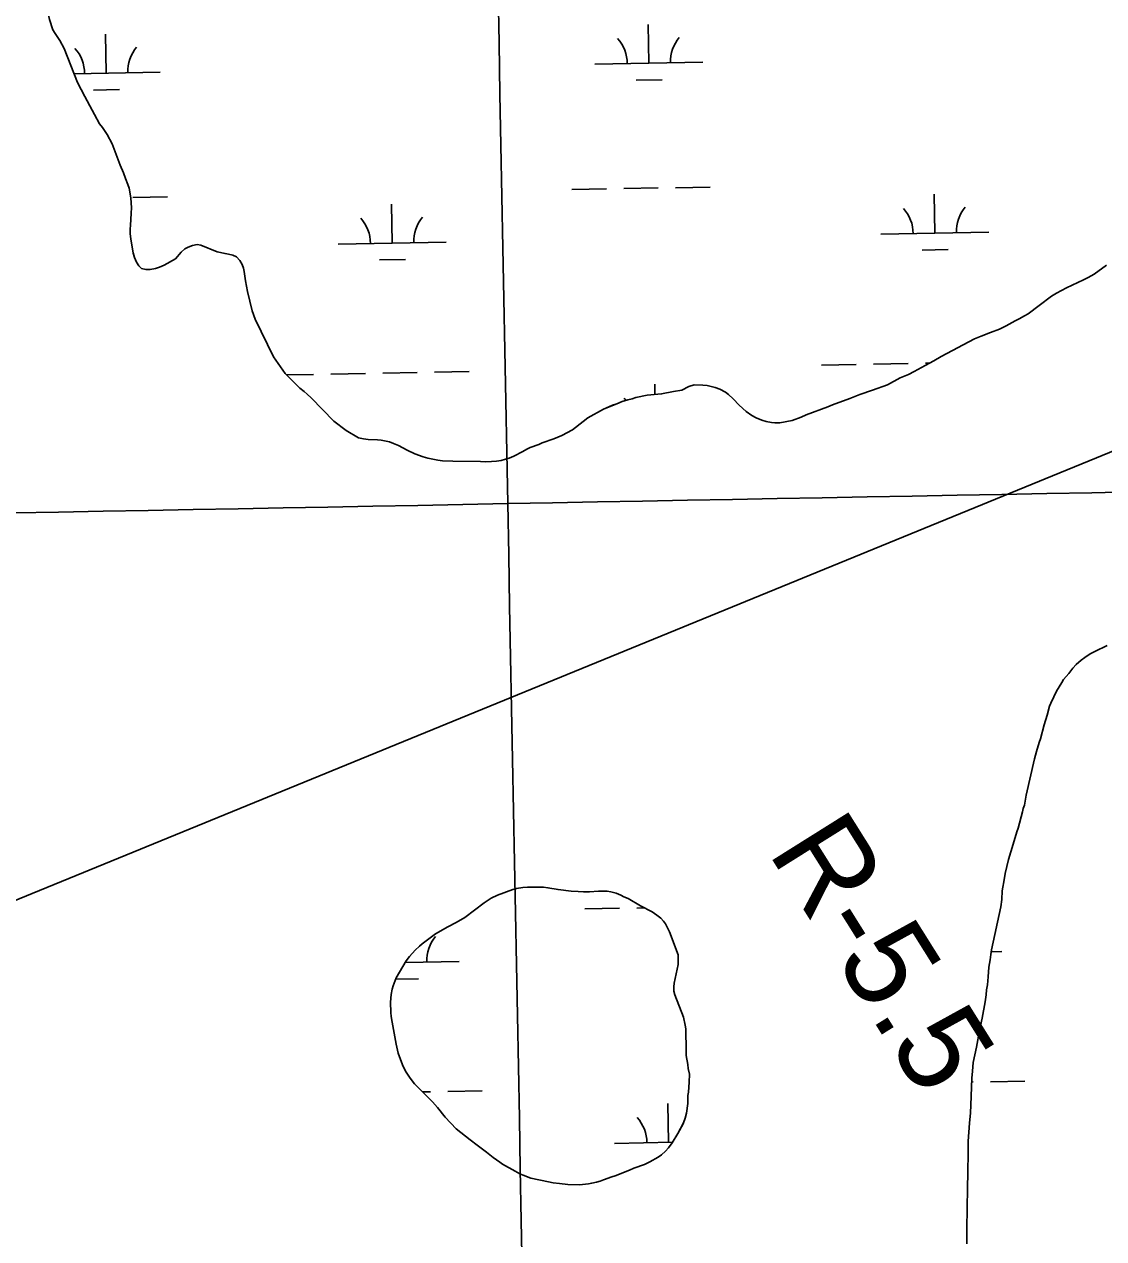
# Model space of a CAD drawing. Extents: x 3957609 to 3995875, y 234277 to 260273.
# Drawn here: x 3971894 to 3972892, y 248308 to 249431 of the extents above; entities that cross this region are included whole.
import ezdxf

# ---------------------------------------------------------------- set-up
doc = ezdxf.new("R2010")
doc.units = 0
for name, color, linetype in [('V-GRID-MAJR', 7, 'Continuous'), ('V-RIVR-RANG-IDEN', 7, 'Continuous'), ('V-TOPO-SHOR', 7, 'Continuous'), ('V-UTIL-LINE', 7, 'Continuous'), ('V-WETL-SWMP', 7, 'Continuous')]:
    doc.layers.add(name, color=color, linetype=linetype)

msp = doc.modelspace()

# ---------------------------------------------------------------- linework, layer by layer
at = {"layer": 'V-GRID-MAJR'}
for points in [[(3972513.068, 239900.828), (3972455.83, 242927.648), (3972341.236, 248987.469), (3972226.642, 255047.279), (3972169.287, 258080.274)], [(3961703.892, 248787.859), (3967022.571, 248887.277), (3972341.236, 248987.469), (3977659.886, 249088.434), (3982978.522, 249190.173), (3988297.143, 249292.685), (3993615.748, 249395.971), (3993615.749, 249395.971)]]:
    msp.add_spline(points, degree=3, dxfattribs=at)
at = {"layer": 'V-TOPO-SHOR'}
for points in [[(3971943.26, 249377.053), (3971930.929, 249408.423), (3971927.134, 249415.652), (3971922.706, 249422.265), (3971920.73, 249425.724), (3971917.592, 249435.129), (3971913.912, 249450.153), (3971911.655, 249455.957), (3971909.298, 249465.347), (3971908.255, 249468.794), (3971906.965, 249476.611), (3971906.091, 249480.834), (3971905.673, 249484.27), (3971905.583, 249488.794), (3971904.374, 249502.223), (3971904.288, 249507.058), (3971904.583, 249527.327), (3971905.333, 249535.894), (3971906.328, 249540.091), (3971910.924, 249555.774), (3971912.597, 249563.704), (3971912.251, 249564.875)], [(3972072.607, 249220.316), (3972057.569, 249226.46), (3972054.145, 249226.978), (3972049.768, 249226.261), (3972045.688, 249224.604), (3972042.705, 249223.089), (3972039.229, 249220.021), (3972033.994, 249214.014), (3972023.459, 249208.085), (3972019.378, 249206.117), (3972015.46, 249204.925), (3972010.614, 249204.061), (3972006.713, 249203.961), (3972002.672, 249204.956), (3972000.213, 249207.332), (3971998.081, 249210.793), (3971996.117, 249215.188), (3971994.927, 249219.259), (3971992.619, 249232.082), (3971992.072, 249237.392), (3971992.133, 249241.601), (3971992.49, 249244.716), (3971993.122, 249256.09), (3971993.192, 249260.924), (3971992.86, 249270.285), (3971991.122, 249279.356), (3971990.077, 249282.647), (3971987.82, 249288.293), (3971986.022, 249293.311), (3971983.007, 249300.528), (3971975.342, 249320.289), (3971970.787, 249328.932), (3971966.668, 249335.229), (3971963.756, 249338.705), (3971959.046, 249347.194), (3971957.078, 249351.277), (3971950.086, 249363.854), (3971943.26, 249377.053)], [(3972787.81, 249145.832), (3972779.18, 249142.213), (3972772.753, 249139.969), (3972741.945, 249123.417), (3972735.183, 249119.46), (3972727.171, 249115.366), (3972717.105, 249109.587), (3972711.919, 249106.855), (3972704.231, 249103.69), (3972692.445, 249097.469), (3972678.647, 249092.365), (3972666.736, 249088.328), (3972657.483, 249084.72), (3972641.646, 249078.869), (3972637.409, 249077.058), (3972617.339, 249069.552), (3972612.472, 249067.439), (3972604.162, 249064.285), (3972592.904, 249062.266), (3972588.382, 249062.175), (3972585.111, 249062.534), (3972580.135, 249063.541), (3972576.252, 249064.535), (3972570.982, 249066.949), (3972567.115, 249069.034), (3972561.711, 249072.698), (3972555.401, 249078.562), (3972549.716, 249084.415), (3972545.407, 249088.376), (3972542.632, 249090.6), (3972537.368, 249093.326), (3972533.182, 249094.948), (3972525.564, 249096.617), (3972521.672, 249097.141), (3972513.566, 249097.26), (3972508.868, 249095.924), (3972502.268, 249092.433), (3972494.45, 249091.142), (3972483.502, 249088.961), (3972470.231, 249087.907), (3972459.751, 249085.719), (3972456.3, 249084.368), (3972452.389, 249083.489), (3972447.217, 249081.849), (3972442.042, 249079.739), (3972438.122, 249078.394), (3972429.807, 249074.926), (3972415.34, 249066.716), (3972411.08, 249063.347), (3972400.992, 249055.851), (3972391.245, 249050.535), (3972383.871, 249047.522), (3972373.211, 249043.623), (3972370.071, 249042.265), (3972361.918, 249039.264), (3972358.934, 249037.905), (3972355.16, 249035.619), (3972346.99, 249031.527), (3972342.595, 249029.563), (3972339.304, 249028.521), (3972335.235, 249027.488), (3972330.856, 249026.614), (3972326.174, 249026.372), (3972320.559, 249026.297), (3972316.039, 249026.52), (3972290.625, 249026.888), (3972280.961, 249027.183), (3972276.6, 249027.716), (3972267.272, 249029.565), (3972262.922, 249030.72), (3972255.477, 249033.637), (3972248.197, 249037.018), (3972240.148, 249041.19), (3972235.655, 249043.125), (3972231.776, 249044.585), (3972224.313, 249046.097), (3972220.889, 249046.615), (3972212.16, 249046.897), (3972207.802, 249047.43), (3972203.137, 249048.431), (3972191.692, 249054.991), (3972180.59, 249063.732), (3972159.383, 249085.404), (3972155.689, 249088.734), (3972152.92, 249091.267), (3972149.063, 249094.286), (3972135.538, 249107.895), (3972124.534, 249123.339), (3972107.571, 249158.051), (3972105.031, 249165.728), (3972100.456, 249183.575), (3972098.728, 249193.424), (3972097.605, 249202.017), (3972096.872, 249205.302), (3972095.52, 249208.755), (3972093.386, 249212.216), (3972090.319, 249215.691), (3972087.064, 249217.141), (3972083.179, 249218.135), (3972079.913, 249218.649), (3972072.607, 249220.316)], [(3972894.914, 249207.905), (3972883.411, 249199.65), (3972878.063, 249196.608), (3972873.664, 249194.333), (3972857.962, 249187.077), (3972848.689, 249182.063), (3972844.128, 249179.323), (3972832.772, 249170.599), (3972822.37, 249163.107), (3972819.222, 249161.127), (3972814.035, 249158.239), (3972810.58, 249156.574), (3972802.246, 249152.015), (3972799.107, 249150.502), (3972795.961, 249148.677), (3972787.81, 249145.832)], [(3972765.913, 248303.15), (3972765.72, 248311.391), (3972766.161, 248341.695), (3972766.423, 248348.998), (3972766.795, 248374.641), (3972767.056, 248381.789), (3972766.967, 248386.452), (3972767.135, 248398.107), (3972768.309, 248414.569), (3972769.222, 248424.037), (3972769.64, 248431.336), (3972770.312, 248456.199), (3972771.027, 248462.562), (3972771.242, 248466.756), (3972771.768, 248470.789), (3972774.613, 248484.738), (3972777.48, 248500.241), (3972779.976, 248511.552), (3972782.684, 248526.746), (3972783.714, 248533.417), (3972784.087, 248537.763), (3972784.777, 248542.416), (3972785.662, 248549.864), (3972786.258, 248558.716), (3972787.443, 248565.54), (3972787.982, 248570.506), (3972788.666, 248574.848), (3972797.171, 248614.517), (3972798.204, 248621.343), (3972798.478, 248629.576), (3972798.992, 248632.835), (3972799.994, 248637.637), (3972801.196, 248645.393), (3972804.339, 248658.56), (3972808.738, 248672.486), (3972812.015, 248684.096), (3972813.308, 248687.342), (3972817.258, 248702.518), (3972817.926, 248705.619), (3972819.058, 248708.711), (3972820.746, 248717.858), (3972828.229, 248751.48), (3972829.212, 248755.041), (3972830.349, 248758.289), (3972832.647, 248766.649), (3972833.783, 248770.053), (3972837.234, 248782.904), (3972840.009, 248792.036), (3972842.305, 248800.24), (3972843.434, 248803.024), (3972846.162, 248808.889), (3972848.724, 248813.982), (3972853.506, 248822.152), (3972855.253, 248824.769), (3972859.998, 248830.45), (3972863.801, 248835.37), (3972866.959, 248838.745), (3972871.524, 248842.72), (3972874.823, 248845.159), (3972879.847, 248848.506), (3972884.076, 248850.777), (3972895.658, 248856.204)], [(3972233.511, 248533.726), (3972234.358, 248538.389), (3972235.182, 248541.494), (3972237.94, 248548.936), (3972247.367, 248564.7), (3972250.542, 248568.708), (3972255.774, 248574.71), (3972259.725, 248578.395), (3972262.248, 248580.539), (3972274.54, 248589.714), (3972285.857, 248596.098), (3972293.712, 248600.192), (3972301.729, 248604.906), (3972319.537, 248618.21), (3972325.836, 248622.64), (3972331.8, 248625.36), (3972346.065, 248630.762), (3972349.505, 248631.649), (3972355.287, 248632.501), (3972359.653, 248632.749), (3972364.955, 248632.827), (3972374.462, 248632.689), (3972378.353, 248632.321), (3972387.838, 248630.625), (3972399.818, 248629.046), (3972406.364, 248628.952), (3972411.191, 248628.571), (3972416.8, 248628.489), (3972425.228, 248629.146), (3972433.178, 248629.185), (3972436.598, 248628.514), (3972441.567, 248627.195), (3972445.909, 248625.573), (3972448.534, 248623.975), (3972452.718, 248622.2), (3972464.158, 248615.642), (3972474.831, 248609.875), (3972479.154, 248607.007), (3972482.697, 248604.148), (3972485.308, 248601.461), (3972487.141, 248598.94), (3972490.932, 248591.559), (3972498.884, 248570.244), (3972498.993, 248566.969), (3972498.753, 248561.206), (3972495.231, 248544.109), (3972494.715, 248540.687), (3972494.966, 248536.63), (3972495.696, 248533.189), (3972503.656, 248512.498), (3972505.266, 248505.148), (3972505.841, 248501.867), (3972505.878, 248493.759), (3972506.28, 248489.077), (3972506.103, 248477.078), (3972507.699, 248468.792), (3972508.115, 248465.202), (3972509.286, 248460.041), (3972509.175, 248452.404), (3972508.422, 248443.374), (3972507.908, 248440.263), (3972507.801, 248432.94), (3972506.421, 248423.763), (3972505.421, 248419.255), (3972503.632, 248414.137), (3972498.667, 248405.013), (3972493.242, 248396.518), (3972489.904, 248391.89), (3972487.207, 248388.656), (3972483.416, 248385.281), (3972480.424, 248383.143), (3972472.567, 248378.891), (3972467.699, 248376.468), (3972457.826, 248372.872), (3972453.746, 248371.059), (3972440.58, 248365.952), (3972437.604, 248365.059), (3972429.922, 248362.052), (3972426.635, 248361.01), (3972423.188, 248359.967), (3972418.969, 248359.251), (3972415.998, 248358.513), (3972407.566, 248357.545), (3972396.816, 248358.014), (3972389.189, 248358.747), (3972383.277, 248359.455), (3972378.927, 248360.455), (3972362.762, 248363.652), (3972355.473, 248366.406), (3972352.379, 248367.854), (3972348.047, 248370.101), (3972336.294, 248376.663), (3972333.828, 248378.569), (3972327.655, 248382.866), (3972321.646, 248387.787), (3972316.715, 248391.599), (3972312.856, 248394.304), (3972306.534, 248399.074), (3972293.591, 248409.394), (3972283.457, 248420.142), (3972276.261, 248428.975)], [(3972276.261, 248428.975), (3972271.659, 248434.187), (3972258.289, 248447.474), (3972255.07, 248451.106), (3972251.093, 248456.307), (3972247.275, 248461.819), (3972245.756, 248464.491), (3972243.943, 248468.571), (3972239.89, 248479.229), (3972237.983, 248487.519), (3972234.383, 248507.993), (3972233.527, 248513.303), (3972233.113, 248517.051), (3972232.937, 248526.406), (3972233.511, 248533.726)]]:
    msp.add_lwpolyline(points, dxfattribs=at)
at = {"layer": 'V-UTIL-LINE'}
msp.add_lwpolyline([(3961767.682, 245361.868), (3961943.705, 245468.964), (3965208.639, 247597.169), (3966396.749, 247622.307), (3967484.854, 247669.667), (3969697.646, 247716.332), (3970569.601, 248052.102), (3971717.759, 248552.062), (3975420.027, 250066.441), (3979384.42, 251663.69), (3984441.626, 253334.756), (3993476.194, 256555.397)], dxfattribs=at)
at = {"layer": 'V-WETL-SWMP'}
for p, q in [((3972471.801, 249394.673), (3972471.146, 249430.667)), ((3971969.975, 249385.548), (3971969.321, 249421.542)), ((3971940.134, 249385.005), (3972019.967, 249386.457)), ((3972421.809, 249393.764), (3972521.792, 249395.582)), ((3972460.083, 249379.026), (3972484.079, 249379.462)), ((3971958.258, 249369.901), (3971982.254, 249370.338)), ((3972400.503, 249277.925), (3972432.498, 249278.507)), ((3972448.495, 249278.798), (3972480.49, 249279.379)), ((3972496.487, 249279.67), (3972528.482, 249280.252)), ((3972736.136, 249237.59), (3972735.482, 249273.584)), ((3971994.662, 249270.546), (3972026.657, 249271.127)), ((3972234.311, 249228.466), (3972233.656, 249264.46)), ((3972184.319, 249227.557), (3972284.303, 249229.375)), ((3972686.144, 249236.681), (3972786.128, 249238.499)), ((3972724.419, 249221.944), (3972748.415, 249222.38)), ((3972222.593, 249212.819), (3972246.59, 249213.255)), ((3972631.493, 249115.597), (3972663.487, 249116.178)), ((3972679.485, 249116.469), (3972711.479, 249117.051)), ((3972727.477, 249117.342), (3972731.169, 249117.409)), ((3972136.824, 249106.602), (3972161.662, 249107.054)), ((3972177.66, 249107.345), (3972209.654, 249107.926)), ((3972225.652, 249108.217), (3972257.646, 249108.799)), ((3972273.644, 249109.09), (3972305.638, 249109.672)), ((3972477.368, 249088.474), (3972477.194, 249098.047)), ((3972412.599, 248612.685), (3972444.594, 248613.267)), ((3972460.591, 248613.558), (3972467.773, 248613.688)), ((3972788.389, 248573.08), (3972798.224, 248573.259)), ((3972246.486, 248563.227), (3972296.399, 248564.134)), ((3972237.456, 248547.629), (3972258.686, 248548.015)), ((3972770.216, 248452.659), (3972771.568, 248452.684)), ((3972787.565, 248452.975), (3972819.56, 248453.556)), ((3972262.364, 248443.425), (3972269.742, 248443.559)), ((3972285.74, 248443.85), (3972317.735, 248444.432)), ((3972489.945, 248396.813), (3972489.29, 248432.807)), ((3972439.953, 248395.904), (3972493.472, 248396.877))]:
    msp.add_line(p, q, dxfattribs=at)
for points in [[(3972093.386, 249212.216), (3972090.318, 249215.691), (3972087.064, 249217.142), (3972083.18, 249218.134), (3972079.912, 249218.649), (3972072.607, 249220.315), (3972057.569, 249226.46), (3972054.145, 249226.977), (3972049.768, 249226.261), (3972045.689, 249224.605), (3972042.704, 249223.089), (3972039.229, 249220.02), (3972033.995, 249214.014), (3972023.46, 249208.085), (3972019.377, 249206.117), (3972015.461, 249204.926), (3972010.614, 249204.061), (3972006.714, 249203.961), (3972002.673, 249204.956), (3972000.213, 249207.331), (3971998.08, 249210.793), (3971996.116, 249215.188), (3971994.927, 249219.26), (3971992.618, 249232.081), (3971992.072, 249237.392), (3971992.133, 249241.601), (3971992.49, 249244.715), (3971993.123, 249256.091), (3971993.193, 249260.924), (3971992.861, 249270.286), (3971991.122, 249279.356), (3971990.078, 249282.647), (3971987.821, 249288.294), (3971986.022, 249293.31), (3971983.008, 249300.528), (3971975.341, 249320.289), (3971970.788, 249328.932), (3971966.669, 249335.23), (3971963.756, 249338.704), (3971959.045, 249347.193), (3971957.077, 249351.277), (3971950.086, 249363.854), (3971943.26, 249377.053), (3971930.928, 249408.423), (3971927.134, 249415.652), (3971922.707, 249422.266), (3971920.73, 249425.725), (3971917.592, 249435.128)], [(3972814.034, 249158.239), (3972810.579, 249156.573), (3972802.247, 249152.016), (3972799.106, 249150.502), (3972795.961, 249148.676), (3972787.81, 249145.832), (3972779.18, 249142.214), (3972772.753, 249139.968), (3972741.946, 249123.417), (3972735.183, 249119.46), (3972727.17, 249115.366), (3972717.105, 249109.586), (3972711.919, 249106.854), (3972704.232, 249103.691), (3972692.445, 249097.468), (3972678.647, 249092.366), (3972666.736, 249088.329), (3972657.483, 249084.72), (3972641.646, 249078.868), (3972637.409, 249077.058), (3972617.339, 249069.552), (3972612.473, 249067.439), (3972604.162, 249064.285), (3972592.904, 249062.265), (3972588.381, 249062.175), (3972585.111, 249062.534), (3972580.135, 249063.542), (3972576.251, 249064.535), (3972570.983, 249066.95), (3972567.115, 249069.034), (3972561.71, 249072.699), (3972555.401, 249078.561), (3972549.716, 249084.414), (3972545.407, 249088.375), (3972542.632, 249090.599), (3972537.369, 249093.326), (3972533.182, 249094.947), (3972525.564, 249096.617), (3972521.673, 249097.141), (3972513.566, 249097.259), (3972508.868, 249095.924), (3972502.267, 249092.433), (3972494.451, 249091.143), (3972483.502, 249088.962), (3972470.231, 249087.907), (3972459.751, 249085.72), (3972456.3, 249084.367), (3972452.389, 249083.488), (3972447.218, 249081.848), (3972442.041, 249079.74), (3972438.123, 249078.393), (3972429.807, 249074.927), (3972415.34, 249066.716), (3972411.081, 249063.346), (3972400.991, 249055.851), (3972391.245, 249050.535), (3972383.871, 249047.523), (3972373.21, 249043.623), (3972370.071, 249042.265), (3972361.918, 249039.264), (3972358.935, 249037.904), (3972355.159, 249035.62), (3972346.99, 249031.528), (3972342.595, 249029.564), (3972339.305, 249028.52), (3972335.235, 249027.488), (3972330.856, 249026.615), (3972326.174, 249026.372), (3972320.559, 249026.297), (3972316.039, 249026.519), (3972290.625, 249026.888), (3972280.96, 249027.184), (3972276.601, 249027.715), (3972267.271, 249029.566), (3972262.921, 249030.721), (3972255.478, 249033.636), (3972248.197, 249037.017), (3972240.148, 249041.189), (3972235.654, 249043.125), (3972231.776, 249044.585), (3972224.312, 249046.097), (3972220.889, 249046.615), (3972212.16, 249046.898), (3972207.801, 249047.429), (3972203.137, 249048.432), (3972191.692, 249054.992), (3972180.59, 249063.731), (3972159.384, 249085.404), (3972155.689, 249088.733), (3972152.919, 249091.268), (3972149.064, 249094.287), (3972135.538, 249107.896), (3972124.534, 249123.339), (3972107.571, 249158.05), (3972105.032, 249165.729), (3972100.456, 249183.574), (3972098.728, 249193.424), (3972097.605, 249202.018), (3972096.873, 249205.303), (3972095.52, 249208.754), (3972093.386, 249212.216)], [(3972894.914, 249207.904), (3972883.41, 249199.65), (3972878.063, 249196.609), (3972873.664, 249194.333), (3972857.963, 249187.076), (3972848.689, 249182.064), (3972844.127, 249179.323), (3972832.772, 249170.599), (3972822.37, 249163.108), (3972819.222, 249161.127), (3972814.034, 249158.239)], [(3972765.913, 248303.149), (3972765.721, 248311.391), (3972766.161, 248341.696), (3972766.423, 248348.998), (3972766.795, 248374.641), (3972767.055, 248381.788), (3972766.967, 248386.453), (3972767.136, 248398.108), (3972768.308, 248414.569), (3972769.223, 248424.037), (3972769.64, 248431.337), (3972770.312, 248456.199), (3972771.026, 248462.562), (3972771.242, 248466.756), (3972771.767, 248470.789), (3972774.612, 248484.738), (3972777.48, 248500.241), (3972779.976, 248511.552), (3972782.684, 248526.747), (3972783.713, 248533.416), (3972784.087, 248537.763), (3972784.777, 248542.416), (3972785.662, 248549.865), (3972786.257, 248558.716), (3972787.444, 248565.539), (3972787.983, 248570.505), (3972788.667, 248574.848), (3972797.171, 248614.518), (3972798.203, 248621.343), (3972798.478, 248629.577), (3972798.992, 248632.834), (3972799.994, 248637.638), (3972801.195, 248645.393), (3972804.34, 248658.56), (3972808.739, 248672.487), (3972812.016, 248684.097), (3972813.307, 248687.343), (3972817.258, 248702.519), (3972817.925, 248705.618), (3972819.058, 248708.711), (3972820.745, 248717.858), (3972828.229, 248751.48), (3972829.213, 248755.041), (3972830.348, 248758.289), (3972832.646, 248766.65), (3972833.784, 248770.053), (3972837.235, 248782.905), (3972840.01, 248792.036), (3972842.305, 248800.241), (3972843.434, 248803.023), (3972846.161, 248808.89), (3972848.723, 248813.983), (3972853.505, 248822.152), (3972855.252, 248824.769), (3972859.998, 248830.451), (3972863.8, 248835.37), (3972866.958, 248838.744), (3972871.524, 248842.72), (3972874.824, 248845.159), (3972879.847, 248848.506), (3972884.077, 248850.776), (3972895.658, 248856.204)], [(3972276.26, 248428.975), (3972271.659, 248434.186), (3972258.29, 248447.474), (3972255.07, 248451.106), (3972251.092, 248456.308), (3972247.275, 248461.819), (3972245.755, 248464.491), (3972243.944, 248468.571), (3972239.89, 248479.229), (3972237.984, 248487.519), (3972234.384, 248507.992), (3972233.526, 248513.304), (3972233.113, 248517.051), (3972232.937, 248526.407), (3972233.511, 248533.725), (3972234.358, 248538.389), (3972235.182, 248541.495), (3972237.941, 248548.937), (3972247.367, 248564.7), (3972250.542, 248568.707), (3972255.774, 248574.71), (3972259.724, 248578.394), (3972262.249, 248580.54), (3972274.541, 248589.714), (3972285.858, 248596.097), (3972293.711, 248600.191), (3972301.73, 248604.907), (3972319.537, 248618.21), (3972325.837, 248622.639), (3972331.8, 248625.359), (3972346.064, 248630.763), (3972349.506, 248631.648), (3972355.286, 248632.5), (3972359.654, 248632.748), (3972364.955, 248632.827), (3972374.462, 248632.689), (3972378.354, 248632.321), (3972387.838, 248630.624), (3972399.818, 248629.047), (3972406.364, 248628.952), (3972411.19, 248628.57), (3972416.801, 248628.489), (3972425.228, 248629.146), (3972433.179, 248629.186), (3972436.598, 248628.513), (3972441.567, 248627.194), (3972445.908, 248625.572), (3972448.535, 248623.975), (3972452.718, 248622.2), (3972464.158, 248615.642), (3972474.83, 248609.875), (3972479.153, 248607.007), (3972482.697, 248604.149), (3972485.308, 248601.462), (3972487.142, 248598.941), (3972490.932, 248591.559), (3972498.884, 248570.244), (3972498.992, 248566.969), (3972498.753, 248561.205), (3972495.231, 248544.109), (3972494.714, 248540.687), (3972494.966, 248536.63), (3972495.696, 248533.19), (3972503.657, 248512.498), (3972505.265, 248505.149), (3972505.841, 248501.867), (3972505.879, 248493.76), (3972506.279, 248489.078), (3972506.104, 248477.078), (3972507.699, 248468.793), (3972508.114, 248465.202), (3972509.286, 248460.04), (3972509.175, 248452.404), (3972508.421, 248443.374), (3972507.908, 248440.264), (3972507.802, 248432.939), (3972506.421, 248423.762), (3972505.421, 248419.256), (3972503.631, 248414.138), (3972498.667, 248405.013), (3972493.243, 248396.518), (3972489.903, 248391.89), (3972487.206, 248388.656), (3972483.415, 248385.281), (3972480.423, 248383.142), (3972472.567, 248378.892), (3972467.699, 248376.468), (3972457.826, 248372.871), (3972453.747, 248371.059), (3972440.579, 248365.951), (3972437.604, 248365.059), (3972429.922, 248362.052), (3972426.634, 248361.009), (3972423.189, 248359.968), (3972418.97, 248359.25), (3972415.998, 248358.514), (3972407.566, 248357.545), (3972396.817, 248358.013), (3972389.189, 248358.747), (3972383.276, 248359.456), (3972378.926, 248360.455)], [(3972378.926, 248360.455), (3972362.761, 248363.651), (3972355.474, 248366.407), (3972352.378, 248367.855), (3972348.046, 248370.1), (3972336.294, 248376.662), (3972333.827, 248378.569), (3972327.655, 248382.867), (3972321.647, 248387.787), (3972316.714, 248391.599), (3972312.856, 248394.305), (3972306.534, 248399.074), (3972293.59, 248409.394), (3972283.458, 248420.141), (3972276.26, 248428.975)]]:
    msp.add_lwpolyline(points, dxfattribs=at)
for centre, start, end in [((3972527.026, 249396.152), 140.269876, 181.813534), ((3971914.733, 249385.018), 0.269879, 41.813537), ((3972025.201, 249387.027), 140.269876, 181.813534), ((3972416.558, 249394.143), 0.269879, 41.813537), ((3972791.361, 249239.069), 140.269876, 181.813534), ((3972179.069, 249227.936), 0.269879, 41.813537), ((3972289.536, 249229.945), 140.269876, 181.813534), ((3972680.894, 249237.061), 0.269879, 41.813537), ((3972422.606, 249061.523), 37.386709, 41.813537), ((3972301.632, 248564.705), 140.269876, 181.813534), ((3972434.702, 248396.283), 0.269879, 41.813537)]:
    msp.add_arc(centre, 35.246, start, end, dxfattribs=at)

# ---------------------------------------------------------------- texts
at = {"layer": 'V-RIVR-RANG-IDEN'}
msp.add_text('R-5.5', height=83, rotation=302.100678, dxfattribs=at).set_placement((3972581.167, 248665.594))

doc.saveas('drawing.dxf')
